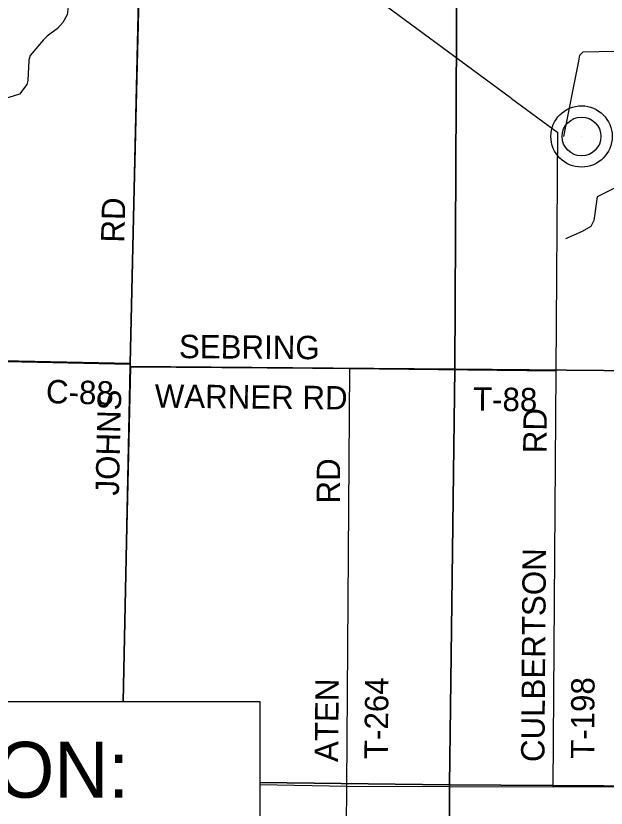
# Model space of a CAD drawing. Extents: x -784 to 1375, y -225 to 440.
# Drawn here: x 328.34 to 357.92, y 300.19 to 339.88 of the extents above; entities that cross this region are included whole.
import ezdxf

# ---------------------------------------------------------------- set-up
doc = ezdxf.new("R2010")
doc.units = 0
for name, color, linetype in [('GM_X_County_Road', 7, 'Continuous'), ('GM_X_County_Road_Text', 7, 'Continuous'), ('GM_X_Minor_River', 7, 'Continuous'), ('GM_X_Section', 7, 'Continuous'), ('GM_X_State_Route', 7, 'Continuous'), ('GM_X_Township_Road', 7, 'Continuous'), ('GM_X_Township_Road_Text', 7, 'Continuous'), ('GM_X_Unincorporated', 7, 'Continuous'), ('GM_X_Unincorporated_Location', 7, 'Continuous'), ('SH_Text', 7, 'Continuous')]:
    doc.layers.add(name, color=color, linetype=linetype)

msp = doc.modelspace()

# ---------------------------------------------------------------- linework, layer by layer
at = {"layer": 'GM_X_County_Road'}
msp.add_lwpolyline([(334.077, 322.408), (326.294, 322.584), (324.958, 322.675), (323.546, 322.713), (323.038, 322.771), (322.649, 322.812), (322.093, 322.886), (321.745, 322.889), (320.697, 322.782), (320.16, 322.679), (318.558, 322.787), (318.819, 336.84)], dxfattribs=at)
at = {"layer": 'GM_X_Minor_River'}
for points in [[(334.304, 348.453), (334.032, 347.737), (333.753, 346.735), (333.662, 345.795), (333.546, 345.31), (333.577, 345.177), (333.531, 345.067), (333.468, 345.059), (332.594, 344.447), (332.165, 344.078), (331.908, 343.655), (331.9, 343.6), (331.863, 342.982), (331.535, 342.645), (331.247, 342.362), (330.99, 341.579), (331.039, 340.78), (330.977, 340.467), (330.908, 339.935), (330.698, 339.551), (330.433, 339.245), (329.902, 338.868), (329.726, 338.681)], [(329.726, 338.681), (329.058, 337.898), (328.983, 337.665), (328.94, 336.647), (328.897, 336.444), (328.519, 335.957), (327.997, 335.794), (327.165, 335.763), (326.948, 335.939), (326.262, 337.441), (326.164, 337.685), (325.957, 337.948), (325.236, 338.455)], [(358.336, 331.242), (357.48, 330.811), (357.308, 329.631), (357.161, 329.32), (356.717, 329.078), (355.893, 328.717)]]:
    msp.add_lwpolyline(points, dxfattribs=at)
at = {"layer": 'GM_X_Section'}
for points in [[(313.882, 343.598), (334.534, 342.899), (334.074, 322.46), (313.315, 322.896)], [(334.534, 342.899), (350.439, 342.394), (350.336, 322.182), (334.071, 322.32), (334.074, 322.46)], [(350.439, 342.394), (355.556, 342.355), (370.946, 342.229), (370.866, 322.002), (350.336, 322.182)], [(370.866, 322.002), (370.703, 301.229), (350.078, 301.357), (350.336, 322.182)]]:
    msp.add_lwpolyline(points, close=True, dxfattribs=at)
for points in [[(312.905, 305.526), (313.315, 322.896), (334.074, 322.46), (334.071, 322.32), (333.718, 305.526)], [(333.718, 305.526), (334.071, 322.32), (350.336, 322.182), (350.078, 301.357), (340.566, 301.475)], [(340.566, 301.475), (350.078, 301.357), (349.986, 283.705)], [(349.986, 283.705), (350.078, 301.357), (370.703, 301.229), (370.671, 283.705)]]:
    msp.add_lwpolyline(points, dxfattribs=at)
at = {"layer": 'GM_X_State_Route'}
for points in [[(344.013, 342.528), (344.349, 342.273), (345.326, 341.547), (353.126, 335.782)], [(353.126, 335.782), (353.18, 335.742), (355.495, 334.041)]]:
    msp.add_lwpolyline(points, dxfattribs=at)
at = {"layer": 'GM_X_Township_Road'}
for p, q in [((333.723, 305.526), (334.105, 322.282)), ((344.776, 283.705), (344.924, 301.294))]:
    msp.add_line(p, q, dxfattribs=at)
for points in [[(334.37, 334.707), (334.37, 334.721), (334.563, 342.837)], [(355.798, 333.833), (356.554, 337.609), (356.61, 337.913), (356.764, 338.073), (360.677, 338.155), (370.907, 338.264)], [(334.335, 333.248), (334.37, 334.707)], [(355.269, 301.252), (355.418, 322.077), (355.495, 334.041)], [(334.077, 322.408), (334.335, 333.248)], [(334.105, 322.282), (334.089, 322.316), (334.077, 322.408)], [(343.213, 322.21), (334.105, 322.282)], [(355.418, 322.077), (345.077, 322.195), (343.213, 322.21)], [(344.924, 301.294), (345.077, 322.195)], [(340.566, 301.366), (344.924, 301.294), (355.269, 301.252)], [(355.269, 301.252), (363.327, 301.295), (365.533, 301.273), (370.737, 301.175)]]:
    msp.add_lwpolyline(points, dxfattribs=at)
at = {"layer": 'GM_X_Unincorporated'}
for radius in [1.535, 0.973]:
    msp.add_circle((356.69, 333.838), radius, dxfattribs=at)
at = {"layer": 'GM_X_Unincorporated_Location'}
msp.add_line((356.69, 333.838), (356.69, 333.838), dxfattribs=at)
at = {"layer": 'SH_Text'}
msp.add_lwpolyline([(293.56, 305.526), (340.566, 305.526), (340.566, 293.38), (293.56, 293.38)], close=True, dxfattribs=at)

# ---------------------------------------------------------------- texts
at = {"layer": 'GM_X_County_Road_Text'}
msp.add_text('C-88', height=1.1719, rotation=358.6274, dxfattribs=at).set_placement((329.84, 320.477))
at = {"layer": 'GM_X_Township_Road_Text'}
for s, rotation, p in [('RD', 88.5189, (333.776, 328.506)), ('SEBRING', 359.5188, (336.509, 322.733)), ('WARNER RD', 359.425, (335.298, 320.253)), ('T-88', 359.2931, (351.244, 320.101)), ('JOHNS', 88.6728, (333.501, 315.837)), ('RD', 89.5054, (354.933, 317.962)), ('RD', 90, (344.591, 315.448)), ('CULBERTSON', 89.5803, (354.83, 302.492)), ('ATEN', 89.4836, (344.488, 302.493)), ('T-264', 89.4381, (346.978, 302.641)), ('T-198', 89.7193, (357.325, 302.651))]:
    msp.add_text(s, height=1.1719, rotation=rotation, dxfattribs=at).set_placement(p)
at = {"layer": 'SH_Text'}
msp.add_text('PROJECT LOCATION:', height=2.8, dxfattribs=at).set_placement((295.32, 300.71))

doc.saveas('drawing.dxf')
